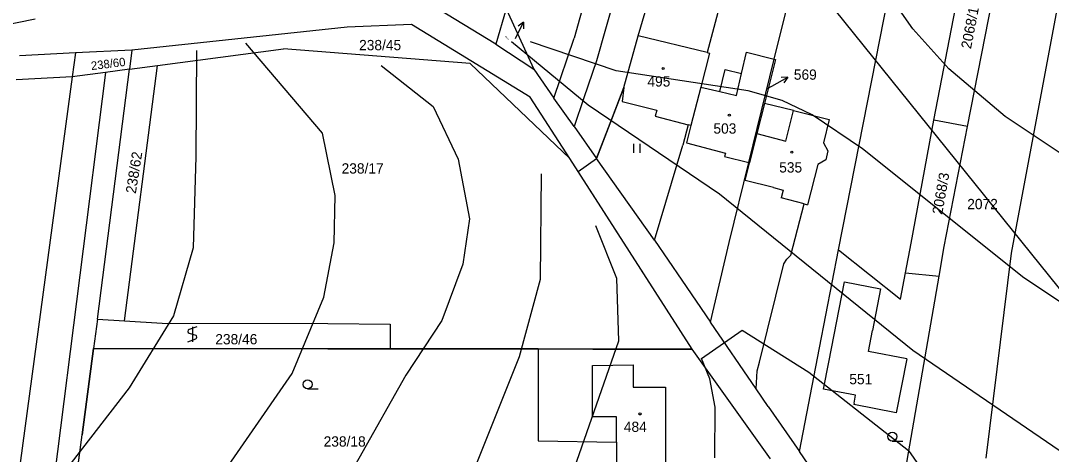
# Model space of a CAD drawing. Extents: x -555860 to -552701, y -1187050 to -1182291.
# Drawn here: x -554621 to -554450.6, y -1184238.2 to -1184166.5 of the extents above; entities that cross this region are included whole.
import ezdxf

# ---------------------------------------------------------------- set-up
doc = ezdxf.new("R2010")
doc.units = 0
for name, color, linetype in [('CYKLISTI_stav', 7, 'Continuous'), ('LEG_2b', 7, 'Continuous'), ('Level 16', 7, 'Continuous'), ('Level 25', 7, 'Continuous'), ('Level 32', 7, 'Continuous'), ('Level 40', 7, 'Continuous'), ('Level 41', 7, 'Continuous'), ('navrh_BV', 7, 'Continuous'), ('Poz předměty', 7, 'Continuous'), ('stav_BV', 7, 'Continuous')]:
    doc.layers.add(name, color=color, linetype=linetype)

msp = doc.modelspace()

# ---------------------------------------------------------------- linework, layer by layer
at = {"layer": 'CYKLISTI_stav'}
for p, q in [((-554507.46, -1184171.8), (-554518.87, -1184169.02)), ((-554502.64, -1184178.89), (-554501.78, -1184175.23)), ((-554521.24, -1184177.54), (-554521.51, -1184179.86)), ((-554505.36, -1184178.25), (-554502.64, -1184178.89)), ((-554521.51, -1184179.86), (-554515.81, -1184181.33)), ((-554515.81, -1184181.33), (-554516.06, -1184182.3)), ((-554494.46, -1184186.41), (-554493.19, -1184181.36)), ((-554516.06, -1184182.3), (-554510.6, -1184183.71)), ((-554510.15, -1184183.83), (-554510.89, -1184186.73)), ((-554499.24, -1184185.15), (-554494.46, -1184186.41)), ((-554510.89, -1184186.73), (-554504.47, -1184188.4)), ((-554504.47, -1184188.4), (-554504.62, -1184188.98)), ((-554504.62, -1184188.98), (-554500.58, -1184189.98)), ((-554501.21, -1184192.92), (-554500.46, -1184190.01)), ((-554496.5, -1184194.11), (-554501.21, -1184192.92)), ((-554491.44, -1184196.81), (-554495.24, -1184195.79)), ((-554487.39, -1184223), (-554484.8, -1184209.67)), ((-554484.8, -1184209.67), (-554478.83, -1184210.84)), ((-554478.83, -1184210.84), (-554480.16, -1184217.75)), ((-554480.83, -1184221.19), (-554480.16, -1184217.75)), ((-554474.48, -1184222.42), (-554480.83, -1184221.19)), ((-554526.44, -1184232), (-554526.41, -1184223.55)), ((-554526.41, -1184223.55), (-554519.69, -1184223.42)), ((-554519.69, -1184223.42), (-554519.73, -1184227.1)), ((-554488.24, -1184227.42), (-554487.39, -1184223)), ((-554474.48, -1184222.42), (-554476.22, -1184231.36)), ((-554519.73, -1184227.1), (-554514.34, -1184227.11)), ((-554514.34, -1184227.11), (-554514.34, -1184242.7)), ((-554482.95, -1184228.45), (-554488.24, -1184227.42)), ((-554483.19, -1184229.74), (-554482.95, -1184228.45)), ((-554483.19, -1184229.74), (-554483.23, -1184229.98)), ((-554476.22, -1184231.36), (-554483.23, -1184229.98)), ((-554522.45, -1184232), (-554526.44, -1184232)), ((-554522.45, -1184236.18), (-554522.45, -1184232))]:
    msp.add_line(p, q, dxfattribs=at)
msp.add_lwpolyline([(-554496.5, -1184194.11), (-554494.9, -1184194.54), (-554495.24, -1184195.79)], dxfattribs=at)
at = {"layer": 'Level 16'}
for p, q in [((-554539.16, -1184169.45), (-554537.85, -1184166.75)), ((-554537.85, -1184166.75), (-554538.74, -1184167.43)), ((-554537.85, -1184166.75), (-554537.84, -1184167.87))]:
    msp.add_line(p, q, dxfattribs=at)
at = {"layer": 'Level 25'}
for p, q in [((-554519.57, -1184188.36), (-554519.57, -1184186.86)), ((-554518.57, -1184188.36), (-554518.57, -1184186.86)), ((-554591.82, -1184217.11), (-554593.12, -1184217.58)), ((-554592.57, -1184217.11), (-554592.57, -1184219.61)), ((-554593.12, -1184218.19), (-554592.02, -1184218.52)), ((-554593.32, -1184219.61), (-554592.02, -1184219.12)), ((-554573.53, -1184227.39), (-554571.78, -1184227.39)), ((-554476.88, -1184236.02), (-554475.13, -1184236.02))]:
    msp.add_line(p, q, dxfattribs=at)
for centre, radius in [((-554514.75, -1184174.42), 0.175), ((-554503.81, -1184182.15), 0.175), ((-554493.48, -1184188.25), 0.175), ((-554573.53, -1184226.64), 0.75), ((-554518.57, -1184231.53), 0.175), ((-554476.88, -1184235.27), 0.75)]:
    msp.add_circle(centre, radius, dxfattribs=at)
for centre, start, end in [((-554592.99, -1184217.89), 113.579, 246.421), ((-554592.15, -1184218.82), 293.574, 66.426)]:
    msp.add_arc(centre, 0.329, start, end, dxfattribs=at)
at = {"layer": 'Level 32'}
for points in [[(-554597.59, -1184220.73), (-554570.19, -1184220.76), (-554559.89, -1184220.77), (-554535.41, -1184220.79), (-554526.4, -1184220.82), (-554519.59, -1184220.81), (-554509.93, -1184220.84), (-554528.82, -1184191.47), (-554525.77, -1184189.28), (-554523.13, -1184182.45), (-554521.24, -1184177.54), (-554518.87, -1184169.02), (-554513.37, -1184150.34), (-554492.51, -1184157.13), (-554440.16, -1184222.12), (-554434.03, -1184222.84), (-554435.88, -1184238.64)], [(-554628.5, -1184366.61), (-554626.42, -1184349.54), (-554623.01, -1184325.33), (-554620.78, -1184309.35), (-554618.1, -1184289.13), (-554614.83, -1184264.68), (-554612.67, -1184249.06), (-554610.79, -1184234.99), (-554608.89, -1184220.71), (-554597.59, -1184220.73)]]:
    msp.add_lwpolyline(points, dxfattribs=at)
at = {"layer": 'Level 40'}
for points in [[(-554295.27, -1184233.79), (-554312.32, -1184251.94), (-554318.95, -1184257.87), (-554327.14, -1184262.67), (-554341.53, -1184266.76), (-554358.42, -1184268.76), (-554370.6, -1184268.87), (-554380.76, -1184267.89), (-554396, -1184264.22), (-554406.16, -1184260.69), (-554416.32, -1184256.32), (-554428.6, -1184250.11), (-554448.07, -1184238.39), (-554473.48, -1184221.04), (-554505.44, -1184195.21), (-554527.15, -1184180.46), (-554539.81, -1184170.02)], [(-554531.47, -1184246.3), (-554522.1, -1184219.47), (-554522.42, -1184209.15), (-554525.86, -1184200.42)]]:
    msp.add_lwpolyline(points, dxfattribs=at)
at = {"layer": 'Level 41'}
for points in [[(-554438.06, -1184195.78), (-554458.24, -1184182.37), (-554467.55, -1184174.47), (-554473.48, -1184167.84), (-554479.69, -1184158.95), (-554488.6, -1184147.66), (-554492.1, -1184144.13), (-554497.04, -1184141.02), (-554500.71, -1184140.03), (-554504.1, -1184139.89), (-554510.87, -1184141.02), (-554526.03, -1184146.66), (-554547.42, -1184156.77)], [(-554722.26, -1184304.29), (-554701.38, -1184308.1), (-554677.67, -1184310.93), (-554664.97, -1184310.5), (-554657.35, -1184309.66), (-554641.26, -1184305.71), (-554631.67, -1184300.48), (-554625.74, -1184294.98), (-554620.38, -1184288.91), (-554576.07, -1184224.85), (-554570.85, -1184212.23), (-554569.14, -1184203.25), (-554568.98, -1184195.41), (-554571.08, -1184185.12), (-554583.74, -1184170.23)], [(-554283.11, -1184174.19), (-554288.05, -1184179.27), (-554300.47, -1184200.43), (-554309.92, -1184214.54), (-554316.84, -1184222.87), (-554323.75, -1184229.5), (-554328.55, -1184233.17), (-554336.73, -1184238.25), (-554342.1, -1184240.65), (-554351.13, -1184243.19), (-554370.32, -1184244.18), (-554375.96, -1184243.47), (-554394.03, -1184239.52), (-554422.25, -1184227.81), (-554432.98, -1184222.45), (-554447.94, -1184213.84), (-554455.13, -1184209.04), (-554481.8, -1184187.73), (-554490.13, -1184182.09), (-554495.07, -1184179.69), (-554500.71, -1184178.14), (-554522.51, -1184174.82), (-554536.68, -1184170)], [(-554591.88, -1184171.42), (-554592, -1184188.95), (-554592.45, -1184204.09), (-554595.71, -1184215.31), (-554603, -1184227.24), (-554618.98, -1184247.88), (-554634.91, -1184265.06), (-554647.76, -1184277.62), (-554659.61, -1184284.68), (-554664.69, -1184286.51), (-554674.85, -1184288.07), (-554690.09, -1184286.66), (-554703.64, -1184283.27), (-554718.88, -1184277.34)], [(-554561.36, -1184173.92), (-554552.74, -1184180.69), (-554548.63, -1184189.4), (-554546.76, -1184199.25), (-554547.84, -1184206.78), (-554551.32, -1184216.1), (-554557.3, -1184225.13), (-554580.58, -1184266.48), (-554596.25, -1184297.38), (-554608.38, -1184316.85), (-554613.6, -1184323.35), (-554618.83, -1184328.28), (-554627.72, -1184334.92), (-554635.9, -1184338.73), (-554643.51, -1184341.02), (-554656.79, -1184343.1), (-554677.11, -1184343.81), (-554696.3, -1184342.96), (-554707.59, -1184341.55), (-554717.75, -1184339.01)], [(-554723.68, -1184371.89), (-554709.28, -1184375.13), (-554697.99, -1184376.55), (-554685.57, -1184375.98), (-554667.51, -1184373.72), (-554656.22, -1184371.32), (-554643.8, -1184367.23), (-554617.56, -1184353.69), (-554611.07, -1184349.73), (-554595.82, -1184338.87), (-554588.63, -1184332.52), (-554580.72, -1184323.77), (-554575.79, -1184315.73), (-554571.27, -1184305.85), (-554562.8, -1184278.47), (-554556.88, -1184263.94), (-554548.41, -1184246.86), (-554538.48, -1184222.06), (-554535, -1184209.25), (-554534.86, -1184191.85)], [(-554506.19, -1184238.79), (-554506.15, -1184230.44), (-554507.05, -1184225.73), (-554508.39, -1184222.37), (-554501.67, -1184217.66), (-554490.69, -1184224.61), (-554474.18, -1184237.55), (-554456.54, -1184262.95)]]:
    msp.add_lwpolyline(points, dxfattribs=at)
at = {"layer": 'navrh_BV'}
for p, q in [((-554520.24, -1184136.43), (-554529.45, -1184169.42)), ((-554515.54, -1184137.35), (-554525.77, -1184173.13)), ((-554496.38, -1184172.86), (-554489.06, -1184143.08)), ((-554485.74, -1184204.39), (-554474.38, -1184146.42)), ((-554469.99, -1184182.95), (-554463.45, -1184148.64)), ((-554502.69, -1184153.7), (-554507.46, -1184171.8)), ((-554518.87, -1184169.02), (-554514.51, -1184154.19)), ((-554542.43, -1184170.42), (-554553.09, -1184163.89)), ((-554464.43, -1184184.02), (-554460.39, -1184163.25)), ((-554540.7, -1184164.58), (-554542.43, -1184170.42)), ((-554540.7, -1184164.58), (-554536.13, -1184174.51)), ((-554449.66, -1184164.67), (-554457.25, -1184204.96)), ((-554618.57, -1184166.26), (-554634.27, -1184169.42)), ((-554566.97, -1184167.57), (-554602.56, -1184171.37)), ((-554556.34, -1184167.17), (-554566.97, -1184167.57)), ((-554536.73, -1184179.16), (-554556.34, -1184167.17)), ((-554532.82, -1184179.3), (-554529.45, -1184169.42)), ((-554521.24, -1184177.54), (-554518.87, -1184169.02)), ((-554542.43, -1184170.42), (-554536.13, -1184174.51)), ((-554611.88, -1184171.85), (-554621.16, -1184172.35)), ((-554611.88, -1184171.85), (-554612.41, -1184175.81)), ((-554602.56, -1184171.37), (-554611.88, -1184171.85)), ((-554602.56, -1184171.37), (-554602.96, -1184174.54)), ((-554598.34, -1184173.93), (-554577.52, -1184171.17)), ((-554546.63, -1184173.61), (-554577.52, -1184171.17)), ((-554507.11, -1184171.88), (-554508.54, -1184177.5)), ((-554507.46, -1184171.8), (-554507.11, -1184171.88)), ((-554501.78, -1184175.23), (-554500.96, -1184171.73)), ((-554500.96, -1184171.73), (-554496.38, -1184172.86)), ((-554500.58, -1184189.98), (-554496.38, -1184172.86)), ((-554496.38, -1184172.86), (-554496.16, -1184172.91)), ((-554608.27, -1184215.84), (-554602.96, -1184174.54)), ((-554602.96, -1184174.54), (-554606.93, -1184175.07)), ((-554603.77, -1184216.13), (-554598.34, -1184173.93)), ((-554602.96, -1184174.54), (-554598.34, -1184173.93)), ((-554530.2, -1184189.32), (-554546.63, -1184173.61)), ((-554536.13, -1184174.51), (-554532.82, -1184179.3)), ((-554525.77, -1184173.13), (-554527.85, -1184179.27)), ((-554496.16, -1184172.91), (-554498, -1184180.21)), ((-554612.41, -1184175.81), (-554624.3, -1184263.98)), ((-554612.41, -1184175.81), (-554621.71, -1184176.31)), ((-554606.93, -1184175.07), (-554616.24, -1184248.57)), ((-554606.93, -1184175.07), (-554612.41, -1184175.81)), ((-554505.36, -1184178.25), (-554504.48, -1184174.59)), ((-554504.48, -1184174.59), (-554501.78, -1184175.23)), ((-554521.24, -1184177.54), (-554525.77, -1184189.28)), ((-554508.54, -1184177.5), (-554510.15, -1184183.83)), ((-554508.54, -1184177.5), (-554505.36, -1184178.25)), ((-554530.2, -1184189.32), (-554536.73, -1184179.16)), ((-554529.44, -1184184.01), (-554532.82, -1184179.3)), ((-554527.85, -1184179.27), (-554529.44, -1184184.01)), ((-554498, -1184180.21), (-554499.24, -1184185.15)), ((-554493.19, -1184181.36), (-554498, -1184180.21)), ((-554493.19, -1184181.36), (-554487.3, -1184182.85)), ((-554487.3, -1184182.85), (-554488.25, -1184186.7)), ((-554473.77, -1184203.32), (-554469.99, -1184182.95)), ((-554464.43, -1184184.02), (-554469.99, -1184182.95)), ((-554529.44, -1184184.01), (-554525.77, -1184189.28)), ((-554510.6, -1184183.71), (-554511.49, -1184187.08)), ((-554510.15, -1184183.83), (-554510.6, -1184183.71)), ((-554468.29, -1184203.85), (-554464.43, -1184184.02)), ((-554499.24, -1184185.15), (-554500.46, -1184190.01)), ((-554516.17, -1184202.78), (-554511.49, -1184187.08)), ((-554488.25, -1184186.7), (-554487.51, -1184188.03)), ((-554487.51, -1184188.03), (-554487.87, -1184189.5)), ((-554509.93, -1184220.84), (-554530.2, -1184189.32)), ((-554516.17, -1184202.78), (-554525.77, -1184189.28)), ((-554487.87, -1184189.5), (-554489.19, -1184190.28)), ((-554503.83, -1184203.19), (-554500.58, -1184189.98)), ((-554500.58, -1184189.98), (-554500.46, -1184190.01)), ((-554489.19, -1184190.28), (-554490.88, -1184196.96)), ((-554493.66, -1184205.3), (-554491.44, -1184196.81)), ((-554491.44, -1184196.81), (-554490.88, -1184196.96)), ((-554516.17, -1184202.78), (-554511.68, -1184209.39)), ((-554506.95, -1184216.38), (-554503.83, -1184203.19)), ((-554474.7, -1184208.23), (-554473.77, -1184203.32)), ((-554488.93, -1184220.63), (-554485.74, -1184204.39)), ((-554485.74, -1184204.39), (-554475.51, -1184212.53)), ((-554469.15, -1184208.78), (-554468.29, -1184203.85)), ((-554457.25, -1184204.96), (-554461.4, -1184238.86)), ((-554498.85, -1184222.95), (-554494.8, -1184206.72)), ((-554494.8, -1184206.72), (-554494.29, -1184205.92)), ((-554494.29, -1184205.92), (-554493.66, -1184205.3)), ((-554475.51, -1184212.53), (-554474.7, -1184208.23)), ((-554474.7, -1184208.23), (-554469.15, -1184208.78)), ((-554511.68, -1184209.39), (-554506.95, -1184216.38)), ((-554475.52, -1184245.5), (-554469.15, -1184208.78)), ((-554608.27, -1184215.84), (-554608.89, -1184220.71)), ((-554608.27, -1184215.84), (-554603.77, -1184216.13)), ((-554603.77, -1184216.13), (-554597.58, -1184216.52)), ((-554597.58, -1184216.52), (-554570.18, -1184216.56)), ((-554570.18, -1184216.56), (-554559.89, -1184216.67)), ((-554559.89, -1184216.67), (-554559.89, -1184220.77)), ((-554499.4, -1184227.37), (-554506.95, -1184216.38)), ((-554608.89, -1184220.71), (-554610.79, -1184234.99)), ((-554559.89, -1184220.77), (-554608.89, -1184220.71)), ((-554535.41, -1184220.79), (-554559.89, -1184220.77)), ((-554535.41, -1184220.79), (-554535.39, -1184236)), ((-554526.4, -1184220.82), (-554535.41, -1184220.79)), ((-554519.59, -1184220.81), (-554526.4, -1184220.82)), ((-554509.93, -1184220.84), (-554519.59, -1184220.81)), ((-554497.03, -1184238.96), (-554509.93, -1184220.84)), ((-554492.24, -1184237.74), (-554488.93, -1184220.63)), ((-554499.22, -1184224.42), (-554498.85, -1184222.95)), ((-554499.4, -1184227.37), (-554499.22, -1184224.42)), ((-554497.39, -1184230.3), (-554499.4, -1184227.37)), ((-554497.39, -1184230.3), (-554492.24, -1184237.74)), ((-554612.67, -1184249.06), (-554610.79, -1184234.99)), ((-554535.39, -1184236), (-554522.45, -1184236.18)), ((-554522.45, -1184236.18), (-554522.45, -1184242.69)), ((-554482.97, -1184251), (-554492.24, -1184237.74))]:
    msp.add_line(p, q, dxfattribs=at)
at = {"layer": 'Poz předměty'}
for points in [[(-554513.37, -1184150.34), (-554492.51, -1184157.13), (-554440.16, -1184222.12)], [(-554528.82, -1184191.47), (-554525.77, -1184189.28)]]:
    msp.add_lwpolyline(points, dxfattribs=at)
at = {"layer": 'stav_BV'}
for p, q in [((-554539.16, -1184169.45), (-554537.84, -1184166.75)), ((-554537.84, -1184166.75), (-554538.73, -1184167.43)), ((-554537.84, -1184166.75), (-554537.83, -1184167.87)), ((-554496.77, -1184177.32), (-554494.15, -1184175.86)), ((-554494.15, -1184175.86), (-554495.26, -1184175.91)), ((-554494.15, -1184175.86), (-554494.78, -1184176.79)), ((-554497.48, -1184177.71), (-554496.77, -1184177.32))]:
    msp.add_line(p, q, dxfattribs=at)

# ---------------------------------------------------------------- texts
at = {"layer": 'LEG_2b'}
for s, height, rotation, p in [('2068/1', 1.7, 79, (-554463.87, -1184171.27)), ('2036/3', 0.2, 310, (-554540.89, -1184169.12)), ('238/60', 1.4, 7, (-554609.24, -1184174.69)), ('238/62', 1.7, 81, (-554601.92, -1184195.19)), ('2068/3', 1.7, 80, (-554468.63, -1184198.65))]:
    msp.add_text(s, height=height, rotation=rotation, dxfattribs=at).set_placement(p)
for s, p in [('238/45', (-554565.01, -1184171.4)), ('569', (-554493.15, -1184176.28)), ('495', (-554517.35, -1184177.41)), ('503', (-554506.44, -1184185.19)), ('238/17', (-554567.9, -1184191.79)), ('535', (-554495.57, -1184191.62)), ('2072', (-554464.49, -1184197.68)), ('238/46', (-554588.78, -1184220.03)), ('551', (-554483.98, -1184226.63)), ('484', (-554521.25, -1184234.51)), ('238/18', (-554570.87, -1184236.93))]:
    msp.add_text(s, height=1.7, dxfattribs=at).set_placement(p)

doc.saveas('drawing.dxf')
